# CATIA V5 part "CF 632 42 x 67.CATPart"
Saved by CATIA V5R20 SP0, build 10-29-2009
Part number: CF 632 42 x 67
Definition: NONE
Nomenclature: CF 632 42 x 67
Source: Unknown
Description: CF 632 42 x 67
Bounding box of the stored display mesh (mm): x -13 to 54, y -31.5 to 31.5, z -31.5 to 31.5
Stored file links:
  C:\Users\Utente\Desktop\IO LAVORO\3D X SITO CF\X SITO\CF 632\CF 632 42 x 67.CATPart
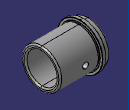
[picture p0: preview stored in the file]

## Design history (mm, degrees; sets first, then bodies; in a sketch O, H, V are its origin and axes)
Body1 "CF 632 42 x 67" (main body)
  Solid1: solid without history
